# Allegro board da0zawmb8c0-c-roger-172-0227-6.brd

Outline 219.8 x 128 mm; copper layers: TOP, SGND, IN1, IN2, SVCC, IN3, SGND1, BOTTOM. Coordinates in mm from the lower left corner of the outline.

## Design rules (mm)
constraint set DEFAULT: min track width 0.102
net group DFP-S6(5)W6.5(5.5)-T13B: nets M_B_CLKN0 M_B_CLKP0
net group W12-T123B: nets +3V_RTC +3VLCD_CON_R_C
net group DFP-S3.5W4(3.5)-T13B: nets PEX_TSTCLK PEX_TSTCLK# VMA_CLK0 VMA_CLK0# VMA_CLK1 VMA_CLK1# VMA_WCK01 VMA_WCK01# VMA_WCK23 VMA_WCK23# VMA_WCK45 VMA_WCK45# VMA_WCK67 VMA_WCK67#
net group DFP-S4.5W4(3.5)-T13B: nets C_IN_CLK C_IN_CLK# C_IN_CLK#_R C_IN_CLK_R C_TX0_HDMI+ C_TX0_HDMI+_R C_TX0_HDMI- C_TX0_HDMI-_R C_TX1_HDMI+ C_TX1_HDMI+_R C_TX1_HDMI- C_TX1_HDMI-_R C_TX2_HDMI+ C_TX2_HDMI+_R C_TX2_HDMI- C_TX2_HDMI-_R CK_XDP_N CK_XDP_P CLK_PCIE_LANN CLK_PCIE_LANP CLK_PCIE_SSDN CLK_PCIE_SSDP CLK_PCIE_WLANN CLK_PCIE_WLANP CLK_VGA_N CLK_VGA_P IN_CLK#_R IN_CLK_R IN_D0#_R IN_D0_R IN_D1#_R IN_D1_R IN_D2#_R IN_D2_R INT_EDP_AUXN INT_EDP_AUXN_C INT_EDP_AUXP INT_EDP_AUXP_C INT_EDP_TXN0 INT_EDP_TXN0_C INT_EDP_TXN1 INT_EDP_TXN1_C INT_EDP_TXN2 INT_EDP_TXN2_C INT_EDP_TXN3 INT_EDP_TXN3_C INT_EDP_TXP0 INT_EDP_TXP0_C INT_EDP_TXP1 INT_EDP_TXP1_C INT_EDP_TXP2 INT_EDP_TXP2_C INT_EDP_TXP3 INT_EDP_TXP3_C INT_HDMICLK+_OUT INT_HDMICLK-_OUT INT_HDMITX0N_OUT INT_HDMITX0P_OUT INT_HDMITX1N_OUT INT_HDMITX1P_OUT INT_HDMITX2N_OUT INT_HDMITX2P_OUT M_A_CLKN0 M_A_CLKN1 M_A_CLKP0 M_A_CLKP1 M_A_DQSN0 M_A_DQSN1 M_A_DQSN2 M_A_DQSN3 M_A_DQSN4 M_A_DQSN5 M_A_DQSN6 M_A_DQSN7 M_A_DQSP0 M_A_DQSP1 M_A_DQSP2 M_A_DQSP3 M_A_DQSP4 M_A_DQSP5 M_A_DQSP6 M_A_DQSP7 M_B_DQSN0 M_B_DQSN1 M_B_DQSN2 M_B_DQSN3 M_B_DQSN4 M_B_DQSN5 M_B_DQSN6 M_B_DQSN7 M_B_DQSP0 M_B_DQSP1 M_B_DQSP2 M_B_DQSP3 M_B_DQSP4 M_B_DQSP5 M_B_DQSP6 M_B_DQSP7 PCIE_RCOMP PCIE_RCOMP_P PCIE_RXN9_LAN PCIE_RXN10_WLAN PCIE_RXN13_SSD PCIE_RXN13_SSD_C PCIE_RXN14_SSD PCIE_RXN14_SSD_C PCIE_RXN15_SSD PCIE_RXN15_SSD_C PCIE_RXN16_SSD PCIE_RXN16_SSD_C PCIE_RXN_LAN_L PCIE_RXP9_LAN PCIE_RXP10_WLAN PCIE_RXP13_SSD PCIE_RXP13_SSD_C PCIE_RXP14_SSD PCIE_RXP14_SSD_C PCIE_RXP15_SSD PCIE_RXP15_SSD_C PCIE_RXP16_SSD PCIE_RXP16_SSD_C PCIE_RXP_LAN_L PCIE_TXN9_LAN PCIE_TXN9_LAN_C PCIE_TXN10_WLAN PCIE_TXN10_WLAN_C PCIE_TXN13_SSD PCIE_TXN13_SSD_C PCIE_TXN14_SSD PCIE_TXN14_SSD_C PCIE_TXN15_SSD PCIE_TXN15_SSD_C PCIE_TXN16_SSD PCIE_TXN16_SSD_C PCIE_TXP9_LAN PCIE_TXP9_LAN_C PCIE_TXP10_WLAN PCIE_TXP10_WLAN_C PCIE_TXP13_SSD PCIE_TXP13_SSD_C PCIE_TXP14_SSD PCIE_TXP14_SSD_C PCIE_TXP15_SSD PCIE_TXP15_SSD_C PCIE_TXP16_SSD PCIE_TXP16_SSD_C PEG_RXN5 PEG_RXN5_C PEG_RXN6 PEG_RXN6_C PEG_RXN7 PEG_RXN7_C PEG_RXN8 PEG_RXN8_C PEG_RXP5 PEG_RXP5_C PEG_RXP6 PEG_RXP6_C PEG_RXP7 PEG_RXP7_C PEG_RXP8 PEG_RXP8_C PEG_TXN5 PEG_TXN5_C PEG_TXN6 PEG_TXN6_C PEG_TXN7 PEG_TXN7_C PEG_TXN8 PEG_TXN8_C PEG_TXP5 PEG_TXP5_C PEG_TXP6 PEG_TXP6_C PEG_TXP7 PEG_TXP7_C PEG_TXP8 PEG_TXP8_C SATA_RXN0_C SATA_RXN0_CN SATA_RXN0_IN SATA_RXN1A_C SATA_RXN1A_ODD SATA_RXN_OUT SATA_RXP0_C SATA_RXP0_CN SATA_RXP0_IN SATA_RXP1A_C SATA_RXP1A_ODD SATA_RXP_OUT SATA_TXN0_C SATA_TXN0_CN SATA_TXN0_IN SATA_TXN1A_C SATA_TXN1A_ODD SATA_TXN_OUT SATA_TXP0_C SATA_TXP0_CN SATA_TXP0_IN SATA_TXP1A_C SATA_TXP1A_ODD SATA_TXP_OUT USB3_SS0RX+ USB3_SS0RX- USB3_SS0TX+ USB3_SS0TX- USB30_RX1+ USB30_RX1+_C USB30_RX1- USB30_RX1-_C USB30_RX2+ USB30_RX2+_C USB30_RX2- USB30_RX2-_C USB30_RX3+ USB30_RX3- USB30_RX+_TYPEC1 USB30_RX+_TYPEC2 USB30_RX-_TYPEC1 USB30_RX-_TYPEC2 USB30_TX1+ USB30_TX1+_C USB30_TX1+_C_R USB30_TX1- USB30_TX1-_C USB30_TX1-_C_R USB30_TX2+ USB30_TX2+_C USB30_TX2+_C_R USB30_TX2- USB30_TX2-_C USB30_TX2-_C_R USB30_TX3+ USB30_TX3- USB30_TX+_TYPEC1 USB30_TX+_TYPEC1_C USB30_TX+_TYPEC2 USB30_TX+_TYPEC2_C USB30_TX-_TYPEC1 USB30_TX-_TYPEC1_C USB30_TX-_TYPEC2 USB30_TX-_TYPEC2_C USBP1+_C USBP1+_C_R USBP1+_U14 USBP1-_C USBP1-_C_R USBP1-_U14 USBP2+ USBP2+_C USBP2- USBP2-_C USBP3+_TPC USBP3-_TPC USBP4+_DB USBP4-_DB USBP5+_CAM USBP5+_CAM_C USBP5-_CAM USBP5-_CAM_C USBP6+_CR USBP6-_CR USBP7+_FP USBP7-_FP USBP8+_TS USBP8-_TS USBP8_TS+_C USBP8_TS-_C USBP10+_BT USBP10-_BT USBP_TYPC+_C USBP_TYPC-_C
net group DFP-S4.54W4(3.5)-T13B: nets CNV_WR_CLK_DN CNV_WR_CLK_DP CNV_WR_LANE0_DN CNV_WR_LANE0_DP CNV_WR_LANE1_DN CNV_WR_LANE1_DP CNV_WT_CLK_DN CNV_WT_CLK_DP CNV_WT_LANE0_DN CNV_WT_LANE0_DP CNV_WT_LANE1_DN CNV_WT_LANE1_DP
net group DFP-S11.5(11: nets MDI0+ MDI0+_1 MDI0- MDI0-_1 MDI1+ MDI1+_1 MDI1- MDI1-_1 MDI2+ MDI2+_1 MDI2- MDI2-_1 MDI3+ MDI3+_1 MDI3- MDI3-_1
net group GND: nets GND
net group W4(3.5)-T13B: nets 3602_VRHOT ACZ_BCLK ACZ_RST# ACZ_SDIN0 ACZ_SDOUT ACZ_SYNC BIOS_WP# DDR4_DRAMRST# DMIC_CLK DMIC_CLK_2 DMIC_CLK_2_R DMIC_CLK_L DMIC_DAT DMIC_DAT_2 DMIC_DAT_2_R DMIC_DAT_L DNBSWON# DRAM_RESET# EC_PWROK H_PROCHOT# H_VCCST_PWRGD H_VCCST_PWRGD_R HOLD# HWPG IMVP_PWRGD INTRUDER#_R JTAG_TCK_PCH JTAG_TDI_PCH JTAG_TDO_PCH JTAG_TMS_PCH JTAGX_PCH M_A_DQ0 M_A_DQ1 M_A_DQ2 M_A_DQ3 M_A_DQ4 M_A_DQ5 M_A_DQ6 M_A_DQ7 M_A_DQ8 M_A_DQ9 M_A_DQ10 M_A_DQ11 M_A_DQ12 M_A_DQ13 M_A_DQ14 M_A_DQ15 M_A_DQ16 M_A_DQ17 M_A_DQ18 M_A_DQ19 M_A_DQ20 M_A_DQ21 M_A_DQ22 M_A_DQ23 M_A_DQ24 M_A_DQ25 M_A_DQ26 M_A_DQ27 M_A_DQ28 M_A_DQ29 M_A_DQ30 M_A_DQ31 M_A_DQ32 M_A_DQ33 M_A_DQ34 M_A_DQ35 M_A_DQ36 M_A_DQ37 M_A_DQ38 M_A_DQ39 M_A_DQ40 M_A_DQ41 M_A_DQ42 M_A_DQ43 M_A_DQ44 M_A_DQ45 M_A_DQ46 M_A_DQ47 M_A_DQ48 M_A_DQ49 M_A_DQ50 M_A_DQ51 M_A_DQ52 M_A_DQ53 M_A_DQ54 M_A_DQ55 M_A_DQ56 M_A_DQ57 M_A_DQ58 M_A_DQ59 M_A_DQ60 M_A_DQ61 M_A_DQ62 M_A_DQ63 M_B_DQ0 M_B_DQ1 M_B_DQ2 M_B_DQ3 M_B_DQ4 M_B_DQ5 M_B_DQ6 M_B_DQ7 M_B_DQ8 M_B_DQ9 M_B_DQ10 M_B_DQ11 M_B_DQ12 M_B_DQ13 M_B_DQ14 M_B_DQ15 M_B_DQ16 M_B_DQ17 M_B_DQ18 M_B_DQ19 M_B_DQ20 M_B_DQ21 M_B_DQ22 M_B_DQ23 M_B_DQ24 M_B_DQ25 M_B_DQ26 M_B_DQ27 M_B_DQ28 M_B_DQ29 M_B_DQ30 M_B_DQ31 M_B_DQ32 M_B_DQ33 M_B_DQ34 M_B_DQ35 M_B_DQ36 M_B_DQ37 M_B_DQ38 M_B_DQ39 M_B_DQ40 M_B_DQ41 M_B_DQ42 M_B_DQ43 M_B_DQ44 M_B_DQ45 M_B_DQ46 M_B_DQ47 M_B_DQ48 M_B_DQ49 M_B_DQ50 M_B_DQ51 M_B_DQ52 M_B_DQ53 M_B_DQ54 M_B_DQ55 M_B_DQ56 M_B_DQ57 M_B_DQ58 M_B_DQ59 M_B_DQ60 M_B_DQ61 M_B_DQ62 M_B_DQ63 PCH_AZ_CODEC_BITCLK PCH_AZ_CODEC_RST# PCH_AZ_CODEC_SDIN0 PCH_AZ_CODEC_SDOUT PCH_AZ_CODEC_SYNC PCH_SPI1_CLK PCH_SPI1_CLK_R PCH_SPI1_SI PCH_SPI1_SI_R PCH_SPI1_SO PCH_SPI1_SO_R PCH_SPI_CS0# PCH_SPI_CS0#_R PCH_SPI_IO2 PCH_SPI_IO3 PEGX_RST# PEGX_RST#_C PEX_TERMP PLTRST# PROC_TRST# PROCHOT# PROCHOT_EC PROCPWRGD RSMRST# SIO_RCIN# SPI_TPM_CS# SYS_PWROK SYS_RESET# TESTMODE USB_OC2# XDP_BPM0 XDP_BPM1 XDP_TCK0 XDP_TDI_CPU XDP_TDO_CPU XDP_TMS_CPU XDP_TRST#_CPU
net group W4(3.5)-T123B: nets 2ND_MBCLK 2ND_MBDATA 5V_HSMBCK 5V_HSMBDT 27M_XTAL_IN 27M_XTAL_OUT 3602_ALERT# 3602_CLK 3602_VDIO BRIGHT CLK_24M_DEBUG CLK_PCI_EC CLK_PCI_EC_R CLK_PCI_LPC_R CNV_BRI_DT CNV_BRI_DT_R CNV_BRI_RSP CNV_BRI_RSP_L CNV_RGI_DT CNV_RGI_DT_R CNV_RGI_RSP CNV_RGI_RSP_L COMP_CORE COMP_GT COMP_SA DDCCLK_RIN DDCDATA_RIN DISP_ON EC_PECI EC_PECR_R FB_SA GPUT_CLK_L GPUT_DATA_L H_CPU_SVIDALRT# H_CPU_SVIDCLK H_CPU_SVIDDAT H_CPU_SVIDDAT_R HDMI_HPD HDMI_HPD_C HDMI_HPD_CON HDMI_MB_HPD_R HDMI_SCLK HDMI_SDATA LAD0_R LFRAME#_R LPC_LAD0 LPC_LAD1 LPC_LAD2 LPC_LAD3 LPC_LFRAME# PCH_BLON_C PCH_DISP_ON PCH_DPST_PWM PCH_LVDS_BLON PCIE_CLKREQ_LAN# PCIE_CLKREQ_SSD# PCIE_CLKREQ_VGA# PCIE_CLKREQ_WLAN# PULSAR_38P4M_REFCLK PULSAR_38P4M_REFCLK_R PWM-VID RGND_CORE RGND_GT RGND_SA RTC_RST# RTC_X1 RTC_X2 SDVO_CLK SDVO_DATA SMB_ME0_CLK SMB_ME0_DAT SMB_ME1_CLK SMB_ME1_DAT SMB_PCH_CLK SMB_PCH_DAT SMB_RUN_CLK SMB_RUN_DAT SRTC_RST# SUSCLK_32K SUSCLK_32KHZ SYS_SHDN# THERMTRIP# THERMTRIP#_CPU TP_I2C_CLK TP_I2C_DATA TP_SMB_CLK TP_SMB_DATA ULT_EDP_HPD ULT_EDP_HPD_R VCCGT_SENSE VCORE_SENSE VCORESS_SENSE VGA_VCCSENSE VGA_VSSSENSE VR_SVID_ALERT#_VCORE VR_SVID_CLK_R VSEN_CORE VSEN_GT VSEN_SA VSSGT_SENSE XCLK_BIASREF XTAL24_IN XTAL24_OUT
net group W4-T13B: nets CFG_RCOMP CNV_WT_RCOMP EDRAM_OPIO_RCOMP EMMC_RCOMP EOPIO_RCOMP PCH_OPI_RCOMP PROC_POPIRCOMP SD_1P8_RCOPM USB2_COMP
net group W4-T123B: nets +1.2VSUS
net group W5(4)-T13B: nets M_A_A0 M_A_A1 M_A_A2 M_A_A3 M_A_A4 M_A_A5 M_A_A6 M_A_A7 M_A_A8 M_A_A9 M_A_A10 M_A_A11 M_A_A12 M_A_A13 M_A_ACT# M_A_ALERT# M_A_BG#0 M_A_BG#1 M_A_BS#0 M_A_BS#1 M_A_CAS# M_A_CKE0 M_A_CKE1 M_A_CS#0 M_A_CS#1 M_A_DIM0_ODT0 M_A_DIM0_ODT1 M_A_PARITY M_A_RAS# M_A_WE#
net group W5(4.5: nets FBA_CMD0 FBA_CMD1 FBA_CMD2 FBA_CMD3 FBA_CMD4 FBA_CMD5 FBA_CMD6 FBA_CMD7 FBA_CMD8 FBA_CMD9 FBA_CMD10 FBA_CMD11 FBA_CMD12 FBA_CMD13 FBA_CMD14 FBA_CMD15 FBA_CMD16 FBA_CMD17 FBA_CMD18 FBA_CMD19 FBA_CMD20 FBA_CMD21 FBA_CMD22 FBA_CMD23 FBA_CMD24 FBA_CMD25 FBA_CMD26 FBA_CMD27 FBA_CMD28 FBA_CMD29 FBA_CMD30 FBA_CMD31
net group W5-T13B: nets EDP_RCOMP
net group W6.5(5.5)-T13B: nets M_B_A0 M_B_A1 M_B_A2 M_B_A3 M_B_A4 M_B_A5 M_B_A6 M_B_A7 M_B_A8 M_B_A9 M_B_A10 M_B_A11 M_B_A12 M_B_A13 M_B_ACT# M_B_ALERT# M_B_BG#0 M_B_BG#1 M_B_BS#0 M_B_BS#1 M_B_CAS# M_B_CKE0 M_B_CS#0 M_B_DIM0_ODT0 M_B_PARITY M_B_RAS# M_B_WE#
net group W6.5(6: nets FBA_DBI0 FBA_DBI1 FBA_DBI2 FBA_DBI3 FBA_DBI4 FBA_DBI5 FBA_DBI6 FBA_DBI7 FBA_EDC0 FBA_EDC1 FBA_EDC2 FBA_EDC3 FBA_EDC4 FBA_EDC5 FBA_EDC6 FBA_EDC7 VMA_DQ0 VMA_DQ1 VMA_DQ2 VMA_DQ3 VMA_DQ4 VMA_DQ5 VMA_DQ6 VMA_DQ7 VMA_DQ8 VMA_DQ9 VMA_DQ10 VMA_DQ11 VMA_DQ12 VMA_DQ13 VMA_DQ14 VMA_DQ15 VMA_DQ16 VMA_DQ17 VMA_DQ18 VMA_DQ19 VMA_DQ20 VMA_DQ21 VMA_DQ22 VMA_DQ23 VMA_DQ24 VMA_DQ25 VMA_DQ26 VMA_DQ27 VMA_DQ28 VMA_DQ29 VMA_DQ30 VMA_DQ31 VMA_DQ32 VMA_DQ33 VMA_DQ34 VMA_DQ35 VMA_DQ36 VMA_DQ37 VMA_DQ38 VMA_DQ39 VMA_DQ40 VMA_DQ41 VMA_DQ42 VMA_DQ43 VMA_DQ44 VMA_DQ45 VMA_DQ46 VMA_DQ47 VMA_DQ48 VMA_DQ49 VMA_DQ50 VMA_DQ51 VMA_DQ52 VMA_DQ53 VMA_DQ54 VMA_DQ55 VMA_DQ56 VMA_DQ57 VMA_DQ58 VMA_DQ59 VMA_DQ60 VMA_DQ61 VMA_DQ62 VMA_DQ63
net group W8-T123B: nets +1.05V_LAN +1.8V_SW +1V8_AON +3V +3V3_TPM +3V_DEEP_SUS +3V_LDO_EC +3V_S5 +3V_WLAN_P +3VPCU_EC +3VSPI +5V_PVDD +5VA +5VPCU +A3VPCU +AZA_VDD +G_SEN_PW +USBPWR0 +USBPWR1 +VCCIO +VCCST +VIN AVDD2 DVDD_IO VCCDSW_1P05 VCCPRIM_1P8
net group W10-T123B: nets +1.05V_DEEP_SUS +1.8V_DEEP_SUS +1.8V_S5 +1V8_GFX_MAIN +3V_EC +3VPCU_ECPLL +TYPEC_VBUS_C +VDDQ_VTT +VGPU_CORE DCPRTC NV_PLLVDD RSET SP_PLLVDD VCCA_19P2_1P05 VCCA_OC_1P05 VCCA_SRC_1P05 VCCA_XTAL_1P05 VCCDSW_3P32
net group W13-T123B: nets +1.35V_GFX
net group W14-T123B: nets +2.5V_SUS
net group W15-T13B: nets SM_RCOMP_0 SM_RCOMP_1 SM_RCOMP_2
net group W15-T123B: nets +3V_DMIC +VCCLDOSRAM_1P24 FB_CAL_PD_VDDQ HP-L2 HP-L3 HP-R2 HP-R3 HP_JD# LINE1-L LINE1-R LINE1-VREFO-L LINE1-VREFO-R MIC2-VREFO SENSEA
net group W20-T123B: nets +3V_LAN +3V_RTC_0 +3V_RTC_1 +3V_RTC_2 +5V_FAN +5V_HDMIC +SMDDR_VREF_DIMM +SMDDR_VREF_DQ1_M1 +VCCPLL +VCCPLL_OC +VCCRTC +VCCSTG +VDDQ FB_CAL_TERM_GND FBA_VREFC_1 FBA_VREFC_2 PBA_PWR PBA_PWR_C PBA_PWR_R SM_VREF SMDDR_VREF_DQ1_M3 VCCAPLL_1.05V VCCDPHY_1P24 VCCDSW_GPIO VCCDUSB_1P05 VCCHDA VCCSPI
net group W30-T123B: nets +5V_KB
net group W40-T123B: nets +1.03_GFX +3VLCD_CON +3VLCD_CON_R +601_VCC L_SPK+ L_SPK+_1 L_SPK- L_SPK-_1 R_SPK+ R_SPK+_1 R_SPK- R_SPK-_1 RING2 SLEEVE VCCMPHYGTAON_1P05
net group W60-T123B: nets +1.05V_LAN_REGOUT
net group W80-T123B: nets +VIN_BLIGHT VCCPRIM_1P05 VCCPRIM_3P3
net group W99-T123B: nets +3V_SSD +5VODD +TYPEC_VBUS +VCC_CORE +VCCSA
nets with their own width: min track width 0.305; nets I2CA_SCL I2CA_SDA

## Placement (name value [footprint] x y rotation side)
C1  0.033u/16V_4  [C0402]  92.06 36.44 0 top
C2  *0.033u/16V_4  [C0402]  92.06 37.4 180 top
C3  *0.1U/16V_2  [C0201]  49.85 31.48 90 top
C5  *0.47u/6.3V_2  [C0201]  67.22 40.15 270 bottom
C6  *0.47u/6.3V_2  [C0201]  81.72 46.57 90 top
C7  *0.1u/16V_2  [C0201]  92.59 29.53 90 bottom
C8  0.01u/50V_4  [C0402]  66.36 44.69 90 top
C9  *10P/50V_4  [C0402]  102.09 54.32 90 bottom
C11  *10U/6.3V_4  [C0402]  84.83 55.52 90 top
C12  10u/6.3V_4  [C0402]  83.87 55.52 90 top
C13  *22U/6.3V_6  [C0603]  107.3 67.85 270 top
C14  10u/6.3V_4  [C0402]  83.77 53.53 270 top
C15  22U/6.3V_6  [C0603]  103.4 64.21 90 bottom
C16  1u/6.3V_2  [C0201]  93.76 56.7 90 top
C17  1u/6.3V_2  [C0201]  93.43 57.69 90 top
C18  1u/6.3V_2  [C0201]  92.34 53.43 180 top
C19  22U/6.3V_6  [C0603]  104.86 63.99 90 bottom
C20  10u/6.3V_4  [C0402]  85.79 55.52 90 top
C21  22U/6.3V_6  [C0603]  88.27 57.95 90 top
C22  1u/6.3V_2  [C0201]  90.53 59.17 0 top
C23  1u/6.3V_2  [C0201]  90.43 57.83 270 top
C24  1u/6.3V_2  [C0201]  81.89 54.97 90 top
C25  1u/6.3V_2  [C0201]  94.65 58.43 90 top
C26  22U/6.3V_6  [C0603]  104.02 67.8 270 bottom
C27  *22U/6.3V_6  [C0603]  112.08 58.08 0 bottom
C28  22U/6.3V_6  [C0603]  105.45 67.8 270 bottom
C29  *330u/2.5V_3528H1.9  [C3528]  114.23 64.43 180 bottom
C30  10u/6.3V_4  [C0402]  84.73 53.53 270 top
C31  10u/6.3V_4  [C0402_2]  81.89 56.69 90 top
C32  1u/6.3V_2  [C0201]  90.46 54.29 270 top
C33  1u/6.3V_2  [C0201]  89.5 54.28 270 top
C34  1u/6.3V_2  [C0201]  90.46 56.02 90 top
C35  1u/6.3V_2  [C0201]  89.34 52.56 90 top
C36  1u/6.3V_2  [C0201]  93.58 55.26 90 top
C37  1u/6.3V_2  [C0201]  95.01 56.98 270 top
C38  1u/6.3V_2  [C0201]  89.47 57.83 270 top
C39  1u/6.3V_2  [C0201]  89.5 56.02 90 top
C40  10u/6.3V_4  [C0402]  90.31 52.56 270 top
C41  10u/6.3V_4  [C0402_2]  81.89 58.41 270 top
C42  10u/6.3V_4  [C0402_2]  86.9 55.54 90 top
C43  10u/6.3V_4  [C0402_2]  87 53.53 270 top
C44  *22U/6.3V_6  [C0603]  110.15 67.85 270 top
C45  10u/6.3V_4  [C0402_2]  85.81 53.53 270 top
C46  *22U/6.3V_6  [C0603]  108.72 67.85 270 top
C47  0.1u/16V_2  [C0201]  81.89 53.25 90 top
C48  *22U/6.3V_6  [C0603]  83.96 57.96 90 top
C49  *22U/6.3V_6  [C0603]  85.39 57.96 90 top
C50  *22U/6.3V_6  [C0603]  112.46 54.72 0 top
C51  *22U/6.3V_6  [C0603]  112.46 53.3 0 top
C52  *22U/6.3V_6  [C0603]  86.83 57.95 90 top
C53  *22U/6.3V_6  [C0603]  88.3 55.31 270 top
C54  *22U/6.3V_6  [C0603]  112.46 51.88 0 top
C55  22U/6.3V_6  [C0603]  106.74 52.82 270 bottom
C56  10u/6.3V_4  [C0402_2]  107.94 47.28 90 top
C57  10u/6.3V_4  [C0402_2]  102.12 45.86 270 top
C58  47U/6.3VS_6  [C0603]  108.27 52.84 270 bottom
C59  47U/6.3VS_6  [C0603]  109.79 52.85 270 bottom
C60  *47U/6.3VS_6  [C0603]  111.31 52.85 270 bottom
C61  47U/6.3VS_6  [C0603]  107.73 63.99 90 bottom
C62  47U/6.3VS_6  [C0603]  106.28 63.99 90 bottom
C63  47U/6.3VS_6  [C0603]  108.29 67.8 270 bottom
C64  47U/6.3VS_6  [C0603]  106.87 67.8 270 bottom
C65  47U/6.3VS_6  [C0603]  109.15 63.99 90 bottom
C66  10u/6.3V_4  [C0402_2]  116.19 59.98 0 top
C67  10u/6.3V_4  [C0402_2]  116.19 58.71 0 top
C68  *22U/6.3V_6  [C0603]  112.08 59.5 0 bottom
C69  10u/6.3V_4  [C0402_2]  100.77 64.63 270 bottom
C70  10u/6.3V_4  [C0402_2]  102.04 64.63 270 bottom
C71  10u/6.3V_4  [C0402_2]  116.19 61.25 0 top
C72  10u/6.3V_4  [C0402_2]  102.5 67.8 90 bottom
C73  *22U/6.3V_6  [C0603]  112.05 60.92 0 bottom
C74  10u/6.3V_4  [C0402]  66.36 69.99 90 top
C75  1u/6.3V_2  [C0201]  64.32 69.99 270 top
C76  1u/6.3V_2  [C0201]  77.4 66.53 90 top
C77  10u/6.3V_4  [C0402]  77.4 53.83 270 top
C78  1u/6.3V_2  [C0201]  83.09 61.84 270 top
C79  1u/6.3V_2  [C0201]  81.98 51.83 180 top
C80  1u/6.3V_2  [C0201]  86.93 48.63 270 top
C81  10u/6.3V_4  [C0402_2]  81.9 61.85 90 top
C82  10u/6.3V_4  [C0402_2]  83.14 60.13 270 top
C83  10u/6.3V_4  [C0402_2]  81.89 60.13 270 top
C84  1u/6.3V_2  [C0201]  103.01 38.42 90 top
C85  1u/6.3V_2  [C0201]  103.74 38.44 90 top
C86  1u/6.3V_2  [C0201]  82.05 50.48 270 top
C87  1u/6.3V_2  [C0201]  77.3 56.07 90 top
C88  1u/6.3V_2  [C0201]  65.34 69.99 270 top
C89  1u/6.3V_2  [C0201]  104.46 38.06 90 top
C90  10u/6.3V_4  [C0402]  65.34 64.63 90 top
C91  10u/6.3V_4  [C0402]  64.32 64.63 90 top
C92  10u/6.3V_4  [C0402]  62.67 76.31 90 top
C93  10u/6.3V_4  [C0402]  65.34 56.63 270 top
C94  *10U/6.3V_4  [C0402]  63.31 69.99 90 top
C95  1u/6.3V_2  [C0201]  77.4 51.78 90 top
C96  1u/6.3V_2  [C0201]  107.55 51.78 270 top
C97  1u/6.3V_2  [C0201]  83.8 52.04 270 top
C98  1u/6.3V_2  [C0201]  86.1 50.32 90 top
C99  1u/6.3V_2  [C0201]  110.07 49.01 90 top
C100  1u/6.3V_2  [C0201]  88.02 50.32 90 top
C101  1u/6.3V_2  [C0201]  84.76 52.04 270 top
C102  1u/6.3V_2  [C0201]  87.06 50.32 90 top
C103  10u/6.3V_4  [C0402_2]  88.32 51.8 90 top
C104  10u/6.3V_4  [C0402]  108.47 51.8 90 top
C105  10u/6.3V_4  [C0402_2]  85.95 51.78 90 top
C106  10u/6.3V_4  [C0402]  84.83 50.32 270 top
C107  10u/6.3V_4  [C0402_2]  87.13 51.78 90 top
C108  10u/6.3V_4  [C0402]  107.2 49.01 270 top
C109  10u/6.3V_4  [C0402]  83.87 50.32 270 top
C110  10u/6.3V_4  [C0402]  109.43 51.8 90 top
C111  10u/6.3V_4  [C0402]  108.22 49.01 270 top
C112  10u/6.3V_4  [C0402]  109.23 49.01 270 top
C113  10u/6.3V_4  [C0402]  106.18 49.01 270 top
C114  10u/6.3V_4  [C0402_2]  111.03 48.93 270 top
C115  10u/6.3V_4  [C0402_2]  110.53 51.8 90 top
C116  1u/6.3V_2  [C0201]  100.65 56.37 270 bottom
C117  1u/6.3V_2  [C0201]  65.34 54.72 270 top
C118  1u/6.3V_2  [C0201]  106.97 47.64 90 top
C119  22U/6.3V_6  [C0603]  109.33 46.82 270 top
C122  1u/6.3V_2  [C0201]  106.26 47.64 270 top
C123  1u/6.3V_2  [C0201]  101.15 45.58 90 top
C124  10u/6.3V_4  [C0402]  64.32 60.44 270 top
C125  10u/6.3V_4  [C0402]  63.31 56.63 90 top
C126  10u/6.3V_4  [C0402]  64.32 56.63 90 top
C127  10u/6.3V_4  [C0402]  63.31 60.44 270 top
C128  10u/6.3V_4  [C0402]  62.29 60.44 270 top
C129  10u/6.3V_4  [C0402]  62.29 69.99 270 top
C130  1u/6.3V_2  [C0201]  62.29 56.63 90 top
C131  1u/6.3V_2  [C0201]  65.34 60.44 270 top
C132  1u/6.3V_2  [C0201]  63.31 64.63 270 top
C133  1u/6.3V_2  [C0201]  62.29 64.63 270 top
C134  47U/6.3VS_6  [C0603]  98.64 78.42 90 top
C135  10u/6.3V_4  [C0402_2]  82 72.68 180 top
C136  10u/6.3V_4  [C0402_2]  84.39 70.21 0 top
C137  10u/6.3V_4  [C0402_2]  90.49 81.39 180 top
C138  22U/6.3V_6  [C0603]  83.15 88.63 90 bottom
C139  22U/6.3V_6  [C0603]  77.79 92.24 180 bottom
C140  22U/6.3V_6  [C0603]  94.55 82.54 180 top
C141  22U/6.3V_6  [C0603]  91.88 82.79 180 top
C142  10u/6.3V_4  [C0402]  90.13 60.96 270 top
C143  10u/6.3V_4  [C0402]  89.44 66.18 90 top
C144  10u/6.3V_4  [C0402_2]  90.28 64.45 270 top
C145  22U/6.3V_6  [C0603]  94.25 84.82 270 top
C146  22U/6.3V_6  [C0603]  92.54 84.82 270 top
C147  22U/6.3V_6  [C0603]  90.97 84.82 270 top
C148  22U/6.3V_6  [C0603]  86.09 88.63 270 bottom
C149  22U/6.3V_6  [C0603]  77.89 90.82 0 bottom
C150  10u/6.3V_4  [C0402_2]  88.58 83.17 90 top
C151  10u/6.3V_4  [C0402_2]  82 71.46 180 top
C152  10u/6.3V_4  [C0402_2]  84.45 68.95 0 top
C153  10u/6.3V_4  [C0402_2]  86.22 68.97 180 top
C154  10u/6.3V_4  [C0402_2]  82 70.24 180 top
C155  10u/6.3V_4  [C0402]  82 67.14 180 top
C156  10u/6.3V_4  [C0402]  82 68.11 180 top
C157  10u/6.3V_4  [C0402_2]  92.14 80.61 270 top
C158  10u/6.3V_4  [C0402]  82 69.12 180 top
C159  22U/6.3V_6  [C0603]  84.67 88.63 90 bottom
C160  22U/6.3V_6  [C0603]  81.21 90.66 0 bottom
C161  22U/6.3V_6  [C0603]  96.43 77.89 0 top
C162  10u/6.3V_4  [C0402_2]  93.53 61.56 270 top
C163  10u/6.3V_4  [C0402]  92.26 63.18 90 top
C164  10u/6.3V_4  [C0402]  92.26 61.02 270 top
C165  10u/6.3V_4  [C0402_2]  90.28 62.72 90 top
C166  22U/6.3V_6  [C0603]  87.39 84.95 0 top
C167  22U/6.3V_6  [C0603]  95.67 84.82 90 top
C168  22U/6.3V_6  [C0603]  81.21 92.09 0 bottom
C169  22U/6.3V_6  [C0603]  100.06 78.42 90 top
C170  22U/6.3V_6  [C0603]  84.67 63.82 270 top
C171  22U/6.3V_6  [C0603]  86.09 63.82 270 top
C172  22U/6.3V_6  [C0603]  87.51 63.82 90 top
C173  22U/6.3V_6  [C0603]  88.96 63.82 90 top
C174  22U/6.3V_6  [C0603]  82.21 64.4 180 top
C175  22U/6.3V_6  [C0603]  82.22 65.93 180 top
C176  22U/6.3V_6  [C0603]  88.25 66.48 270 top
C177  1u/6.3V_2  [C0201]  86.8 83.17 180 bottom
C178  1u/6.3V_2  [C0201]  88.33 83.93 0 bottom
C179  1u/6.3V_2  [C0201]  86.8 83.93 180 bottom
C180  1u/6.3V_2  [C0201]  86.8 82.41 180 bottom
C181  1u/6.3V_2  [C0201]  90.99 83.93 0 bottom
C182  1u/6.3V_2  [C0201]  88.33 83.17 0 bottom
C183  1u/6.3V_2  [C0201]  89.47 83.17 180 bottom
C184  1u/6.3V_2  [C0201]  90.99 82.41 0 bottom
C185  1u/6.3V_2  [C0201]  89.47 83.93 180 bottom
C186  1u/6.3V_2  [C0201]  89.47 82.41 180 bottom
C187  1u/6.3V_2  [C0201]  90.99 83.17 0 bottom
C188  1u/6.3V_2  [C0201]  88.33 82.41 0 bottom
C189  1u/6.3V_2  [C0201]  158.05 31.99 0 top
C190  0.1u/16V_2  [C0201]  163.51 33.51 90 top
C191  *22p/50V_4  [C0402]  161.99 34.56 270 top
C192  0.22u/10V_2  [C0201]  101.28 42.79 0 bottom
C193  0.22u/10V_2  [C0201]  101.28 42.07 0 bottom
C194  0.22u/10V_2  [C0201]  104.33 43.14 0 bottom
C195  0.22u/10V_2  [C0201]  104.33 43.85 0 bottom
C200  0.1u/16V_2  [C0201]  100.65 45.48 0 bottom
C201  0.1u/16V_2  [C0201]  100.65 46.19 0 bottom
C202  0.1u/16V_2  [C0201]  181.49 23.18 90 bottom
C203  0.1u/16V_2  [C0201]  180.78 23.18 90 bottom
C204  *2.2p/50V_4  [C0402]  98.54 35.42 90 top
C205  10P/50V_4  [C0402]  99.17 28.79 180 bottom
C206  15p/50V_4  [C0402]  76.13 30.85 180 bottom
C208  10P/50V_4  [C0402]  100.9 28.79 0 bottom
C209  15p/50V_4  [C0402]  79.67 31.33 0 bottom
C212  *0.1u/16V_2  [C0201]  44.84 22.36 270 top
C213  3p/50V_4  [C0402]  63.94 47.61 180 bottom
C214  3p/50V_4  [C0402]  63.61 49.52 90 bottom
C215  3p/50V_4  [C0402]  64.96 44.56 270 bottom
C216  15p/50V_4  [C0402]  62.93 52.06 0 top
C217  15p/50V_4  [C0402]  64.58 49.52 90 bottom
C218  15p/50V_4  [C0402]  64.83 46.21 180 bottom
C219  0.1u/16V_2  [C0201]  98.64 36.82 0 top
C220  1u/6.3V_2  [C0201]  87.46 30.92 180 bottom
C221  0.1u/16V_2  [C0201]  87.46 31.63 180 bottom
C222  1u/6.3V_2  [C0201]  99.88 35.9 180 top
C223  1u/6.3V_2  [C0201]  85.56 48.55 270 top
C224  1u/6.3V_2  [C0201]  97.09 31.48 180 top
C225  1u/6.3V_2  [C0201]  83.27 48.55 270 top
C226  1u/6.3V_2  [C0201]  101.1 35.06 0 bottom
C227  1u/6.3V_2  [C0201]  99.88 29.45 270 top
C228  4.7u/6.3V_4  [C0402]  82.31 31.48 0 bottom
C229  1u/6.3V_2  [C0201]  83.93 46.26 180 top
C230  10u/6.3V_4  [C0402]  96.96 31.51 0 bottom
C231  3p/50V_4  [C0402]  102.17 39.41 0 top
C232  3p/50V_4  [C0402]  99.88 42.79 270 top
C233  10u/6.3V_4  [C0402]  102.63 28.66 180 bottom
C234  10u/6.3V_4  [C0402]  102.63 29.63 180 bottom
C235  1u/6.3V_2  [C0201]  100.26 45.33 180 top
C236  1u/6.3V_2  [C0201]  84.14 30.8 90 top
C237  1u/6.3V_2  [C0201]  88.43 33.4 180 top
C238  1u/6.3V_2  [C0201]  84.8 48.55 270 top
C239  *0.1u/16V_2  [C0201]  66.41 26.91 0 top
C240  1u/6.3V_2  [C0201]  66.46 26.15 0 top
C241  3p/50V_4  [C0402]  88.78 31.6 180 top
C242  1u/6.3V_2  [C0201]  63.31 28.05 0 bottom
C243  3p/50V_4  [C0402]  89.52 28.48 180 top
C244  1u/6.3V_2  [C0201]  107.58 30.42 0 bottom
C245  47U/6.3V_6  [C0603]  107 31.58 0 bottom
C246  0.1u/16V_2  [C0201]  63.69 23.35 180 top
C247  *10P/50V_4  [C0402]  60.16 26.12 270 bottom
C248  *0.1U/16V_2  [C0201]  115.68 22.85 180 top
C249  *0.1u/6.3V_2  [C0201]  50.23 69.46 180 top
C250  1u/6.3V_4  [C0402]  50.23 61.07 180 top
C251  1u/6.3V_4  [C0402]  47.76 28.94 90 top
C252  1u/6.3V_4  [C0402]  52.64 47.1 0 top
C253  1u/6.3V_4  [C0402]  49.69 28.94 90 top
C254  1u/6.3V_4  [C0402]  58.23 55.74 0 top
C255  1u/6.3V_4  [C0402]  48.73 28.94 90 top
C256  1u/6.3V_4  [C0402]  50.23 63.87 180 top
C257  1u/6.3V_4  [C0402]  50.73 28.94 90 top
C258  1u/6.3V_4  [C0402]  49.85 40.5 270 top
C259  10u/6.3V_4  [C0402]  46.8 28.94 90 top
C260  1u/6.3V_4  [C0402]  50.48 55.87 180 top
C261  10u/6.3V_4  [C0402]  50.73 30.97 270 top
C262  1u/6.3V_4  [C0402]  58.35 65.65 0 top
C263  1u/6.3V_4  [C0402]  58.35 61.2 0 top
C264  0.1u/6.3V_2  [C0201]  49.97 53.58 0 top
C265  2.2U/10V_4  [C0402]  50.35 52.56 180 top
C266  0.022u/25V_4  [C0402]  50.23 44.94 0 top
C267  10u/6.3V_4  [C0402]  58.35 53.71 0 top
C268  10u/6.3V_4  [C0402]  58.48 57.77 0 top
C269  1u/6.3V_4  [C0402]  52.26 29.96 0 top
C270  10u/6.3V_4  [C0402]  50.23 72.5 180 top
C271  1u/6.3V_4  [C0402]  52.26 28.33 0 top
C272  10u/6.3V_4  [C0402]  60.26 69.58 180 top
C273  10u/6.3V_4  [C0402]  52.13 31.3 0 top
C274  10u/6.3V_4  [C0402]  50.23 65.39 180 top
C275  10u/6.3V_4  [C0402]  54.04 31.74 270 top
C276  10u/6.3V_4  [C0402]  58.48 77.2 0 top
C277  10u/6.3V_4  [C0402]  56.2 68.01 0 top
C278  0.1u/6.3V_2  [C0201]  55.94 31.99 90 top
C279  10u/6.3V_4  [C0402]  50.23 68.44 180 top
C280  2.2U/10V_4  [C0402]  55.05 32.12 270 top
C281  68p/50V_4  [C0402]  32.95 34.53 270 top
C282  68p/50V_4  [C0402]  30.16 50.41 180 top
C283  68p/50V_4  [C0402]  46.67 82.79 180 top
C284  68p/50V_4  [C0402]  48.47 96.51 90 top
C285  1u/6.3V_4  [C0402]  43.62 61.45 0 top
C286  1u/6.3V_4  [C0402]  45.65 61.45 0 top
C287  1u/6.3V_4  [C0402]  31.05 99.17 270 top
C288  1u/6.3V_4  [C0402]  26.86 90.28 0 top
C289  1u/6.3V_4  [C0402]  44.38 48.12 0 top
C290  1u/6.3V_4  [C0402]  37.15 99.17 270 top
C291  1u/6.3V_4  [C0402]  41.21 99.17 270 top
C292  1u/6.3V_4  [C0402]  41.21 82.79 180 top
C293  1u/6.3V_4  [C0402]  35.11 99.17 270 top
C294  1u/6.3V_4  [C0402]  26.86 86.73 0 top
C295  1u/6.3V_4  [C0402]  40.07 69.46 180 top
C296  1u/6.3V_4  [C0402]  26.86 92.7 0 top
C297  1u/6.3V_4  [C0402]  39.18 99.17 270 top
C298  1u/6.3V_4  [C0402]  30.16 38.34 0 top
C299  0.022u/25V_4  [C0402]  53.66 99.17 180 top
C300  1u/6.3V_4  [C0402]  45.58 96.51 270 top
C301  10u/6.3V_4  [C0402_2]  26.86 88.89 0 top
C302  10u/6.3V_4  [C0402_2]  33.08 99.17 270 top
C303  1u/6.3V_4  [C0402]  50.35 88.89 180 top
C304  1u/6.3V_4  [C0402]  46.04 69.46 0 top
C305  1u/6.3V_4  [C0402]  34.35 61.33 0 top
C306  1u/6.3V_4  [C0402]  30.16 51.42 0 top
C307  10u/6.3V_4  [C0402_2]  30.19 59.83 0 top
C308  10u/6.3V_4  [C0402_2]  37.91 34.78 0 top
C309  10u/6.3V_4  [C0402_2]  43.37 34.78 0 top
C310  3.3p/50V_4  [C0402]  30.67 88 270 top
C311  10u/6.3V_4  [C0402_2]  30.16 37.2 0 top
C312  0.1u/16V_4  [C0402]  37.27 48.12 180 top
C313  10u/6.3V_4  [C0402_2]  30.16 73.52 0 top
C314  2.2u/6.3V_4  [C0402]  45.4 98.54 90 top
C315  1u/6.3V_4  [C0402]  30.67 79.87 90 top
C316  1u/6.3V_4  [C0402]  50.23 86.35 180 top
C317  0.047u/25V_4  [C0402]  36.13 61.33 180 top
C318  1u/6.3V_4  [C0402]  40.04 61.33 180 top
C319  1u/6.3V_4  [C0402]  39.05 48.12 0 top
C320  0.047u/25V_4  [C0402]  37.65 82.79 180 top
C321  1u/6.3V_4  [C0402]  50.35 90.66 180 top
C322  0.01u/50V_4  [C0402]  36.26 69.46 180 top
C323  0.047u/25V_4  [C0402]  46.42 98.54 270 top
C324  0.01u/50V_4  [C0402]  38.16 69.46 0 top
C325  0.01u/50V_4  [C0402]  46.54 96.51 90 top
C326  0.047u/25V_4  [C0402]  37.91 61.33 0 top
C327  0.01u/50V_4  [C0402]  47.51 96.51 90 top
C328  0.01u/50V_4  [C0402]  50.35 93.33 0 top
C329  1u/6.3V_4  [C0402]  30.16 48.37 0 top
C330  1u/6.3V_4  [C0402]  31.94 34.53 90 top
C331  1u/6.3V_4  [C0402]  49.44 96.51 270 top
C332  1u/6.3V_4  [C0402]  48.45 82.79 180 top
C333  1u/6.3V_4  [C0402]  30.16 49.39 0 top
C334  1u/6.3V_4  [C0402]  28.81 82.97 270 top
C335  1u/6.3V_4  [C0402]  50.4 96.51 270 top
C336  3.3p/50V_4  [C0402]  48.45 98.54 270 top
C337  68p/50V_4  [C0402]  39.43 82.79 0 top
C338  2200p/50V_4  [C0402]  35.49 48.12 180 top
C339  68p/50V_4  [C0402]  45.15 34.78 0 top
C340  2200p/50V_4  [C0402]  46.16 48.12 0 top
C341  1u/6.3V_4  [C0402]  29.83 82.97 270 top
C342  0.1u/16V_4  [C0402]  50.35 81.77 0 top
C343  3.3p/50V_4  [C0402]  50.23 95.11 0 top
C344  10u/6.3V_4  [C0402_2]  30.8 34.53 90 top
C345  10u/6.3V_4  [C0402_2]  30.16 70.85 0 top
C346  68p/50V_4  [C0402]  30.16 72 180 top
C347  EV@22U/6.3VS_4  [C0402]  117.54 122.54 180 bottom
C348  EV@10u/6.3V_4  [C0402]  117.16 121.53 180 bottom
C349  EV@4.7u/6.3V_4  [C0402_2]  119.24 120.43 0 bottom
C350  EV@4.7u/6.3V_4  [C0402_2]  117.16 120.43 180 bottom
C351  EV@1u/6.3V_4  [C0402]  104.07 105.9 270 top
C352  EV@1u/6.3V_4  [C0402]  108.11 105.9 270 top
C353  EV@1u/6.3V_4  [C0402]  109.54 102.09 90 top
C354  EV@1u/6.3V_4  [C0402]  111.26 110.58 270 top
C355  EV@47U/6.3V_6  [C0603]  111.06 120.38 0 bottom
C356  EV@4.7u/6.3V_4  [C0402_2]  113.35 120.38 180 bottom
C357  EV@4.7u/6.3V_4  [C0402_2]  108.16 104.13 90 top
C358  EV@0.22u/10V_4  [C0402]  98.11 109.84 180 top
C359  EV@22u/6.3V_6  [C0603]  108.01 120.38 180 bottom
C360  EV@4.7u/6.3V_4  [C0402_2]  120.58 116.7 0 bottom
C362  EV@1u/6.3V_4  [C0402]  109.03 109.08 90 top
C363  EV@10u/6.3V_4  [C0402]  118.93 121.53 0 bottom
C364  *EV@0.1u/16V_4  [C0402]  100.26 125.34 0 bottom
C365  EV@1u/6.3V_4  [C0402]  104.07 102.35 270 top
C366  EV@4.7u/6.3V_4  [C0402_2]  110.55 108.83 180 top
C367  EV@4.7u/6.3V_4  [C0402_2]  108.16 102.35 270 top
C368  EV@4.7u/6.3V_4  [C0402_2]  100.65 105.14 270 top
C369  EV@4.7u/6.3V_4  [C0402_2]  105.6 100.82 0 top
C370  EV@0.22u/10V_4  [C0402]  98.11 110.81 180 top
C371  EV@0.1u/16V_4  [C0402]  100.52 98.61 270 top
C372  EV@4.7u/6.3V_4  [C0402_2]  107.38 100.82 180 top
C373  EV@4.7u/6.3V_4  [C0402_2]  101.84 102.35 270 top
C374  EV@4.7u/6.3V_4  [C0402_2]  107 105.95 270 top
C375  EV@0.1u/16V_4  [C0402]  102.78 98.54 90 top
C376  EV@4.7u/6.3V_4  [C0402_2]  100.39 96.86 90 top
C377  EV@22U/6.3VS_4  [C0402]  118.3 118.22 90 bottom
C378  EV@1u/6.3V_4  [C0402]  101.48 98.61 270 top
C379  EV@4.7u/6.3V_4  [C0402_2]  120.58 115.43 0 bottom
C380  EV@4.7u/6.3V_4  [C0402_2]  105.57 98.31 0 top
C381  EV@10u/6.3V_4  [C0402]  120.33 118.22 90 bottom
C382  EV@0.22u/10V_4  [C0402]  102.04 119.24 90 top
C383  EV@10u/6.3V_4  [C0402]  119.31 118.22 90 bottom
C384  EV@0.22u/10V_4  [C0402]  101.03 119.24 90 top
C385  EV@220u/2V_7343H1.0  [CC7343]  110.25 123.56 180 top
C386  EV@22u/6.3V_6  [C0603]  103.97 98.82 90 top
C387  EV@47U/6.3V_6  [C0603]  103.72 119.09 180 bottom
C388  EV@10u/6.3V_4  [C0402]  109.49 117.74 180 bottom
C389  *EV@10u/6.3V_4  [C0402]  116.52 123.68 0 bottom
C391  *EV@10u/6.3V_4  [C0402]  116.52 124.7 0 bottom
C392  EV@4.7u/6.3V_4  [C0402_2]  89.09 103.49 180 top
C393  *EV@10u/6.3V_4  [C0402]  106.87 117.84 0 bottom
C394  EV@1u/6.3V_4  [C0402]  97.47 99.94 270 top
C395  EV@1u/6.3V_4  [C0402]  101.28 110.86 270 top
C396  EV@4.7u/6.3V_4  [C0402_2]  106.87 118.99 0 bottom
C397  EV@4.7u/6.3V_4  [C0402_2]  113.35 118.96 180 bottom
C398  EV@0.1u/16V_4  [C0402]  99.4 99.81 270 top
C399  EV@1u/6.3V_4  [C0402]  110.25 110.88 270 top
C400  EV@4.7u/6.3V_4  [C0402_2]  111.29 118.48 0 bottom
C401  EV@0.1u/16V_4  [C0402]  98.44 99.81 270 top
C402  EV@1u/6.3V_4  [C0402]  102.68 108.7 90 top
C403  EV@4.7u/6.3V_4  [C0402_2]  109.49 118.88 180 bottom
C406  EV@4.7u/6.3V_4  [C0402_2]  101.84 100.57 90 top
C407  EV@4.7u/6.3V_4  [C0402_2]  103.57 100.75 180 top
C408  EV@4.7u/6.3V_4  [C0402_2]  101.87 106.29 270 top
C409  EV@4.7u/6.3V_4  [C0402_2]  101.84 104.13 90 top
C410  EV@1u/6.3V_4  [C0402]  107.5 107.73 0 top
C411  EV@1u/6.3V_4  [C0402]  105.17 104.13 90 top
C412  EV@10u/6.3V_4  [C0402]  106.97 102.35 270 top
C413  EV@47U/6.3V_6  [C0603]  116.9 119.49 180 top
C414  *EV@47U/6.3V_6  [C0603]  106.74 120.48 180 top
C415  EV@10u/6.3V_4  [C0402]  100.77 107.43 270 top
C416  EV@47U/6.3V_6  [C0603]  110.3 119.06 180 top
C417  *EV@47U/6.3V_6  [C0603]  116.9 122.8 180 top
C418  EV@10u/6.3V_4  [C0402]  106.97 104.13 90 top
C419  EV@47U/6.3V_6  [C0603]  104.58 109.21 0 top
C420  *EV@47U/6.3V_6  [C0603]  89.98 115.94 180 bottom
C421  EV@10u/6.3V_4  [C0402]  105.17 102.35 270 top
C422  EV@47U/6.3V_6  [C0603]  97.98 105.27 90 top
C423  *EV@47U/6.3V_6  [C0603]  110.3 120.48 0 top
C424  EV@10u/6.3V_4  [C0402]  105.17 105.9 270 top
C425  EV@0.1u/16V_4  [C0402]  99.76 107.99 270 top
C426  EV@47U/6.3V_6  [C0603]  106.74 118.96 0 top
C427  *EV@47U/6.3V_6  [C0603]  116.9 121.14 0 top
C428  EV@10u/6.3V_4  [C0402]  105.6 107.94 0 top
C429  EV@4.7u/6.3V_4  [C0402_2]  99.81 109.76 90 top
C430  EV@10u/6.3V_4  [C0402]  104.07 104.13 90 top
C431  EV@4.7u/6.3V_4  [C0402_2]  98.59 107.68 270 top
C432  EV@10u/6.3V_4  [C0402]  99.38 105.9 90 top
C433  EV@0.1u/16V_4  [C0402]  98.21 121.45 180 bottom
C438  EV@1u/6.3V_4  [C0402]  121.83 93.59 90 top
C439  EV@1u/6.3V_4  [C0402]  110.3 104.79 180 top
C440  EV@1u/6.3V_4  [C0402]  123.12 93.59 90 top
C441  EV@1u/6.3V_4  [C0402]  139.38 105.02 90 top
C442  EV@1u/6.3V_4  [C0402]  136.21 105.02 90 top
C443  EV@10u/6.3V_4  [C0402]  109.41 100.44 180 top
C444  EV@10u/6.3V_4  [C0402]  110.31 103.81 180 top
C445  *EV@22U/6.3V_6  [C0603]  109.94 106.95 180 top
C446  *EV@22U/6.3V_6  [C0603]  121.09 102.73 90 bottom
C447  EV@1u/6.3V_4  [C0402]  109.41 99.43 180 top
C448  EV@10u/6.3V_4  [C0402]  110.3 105.75 180 top
C449  EV@1u/6.3V_4  [C0402]  108.42 98.41 180 top
C450  EV@1u/6.3V_4  [C0402]  107.06 99.17 90 top
C451  EV@22u/6.3V_6  [C0603]  119.44 102.73 90 bottom
C452  EV@0.1u/16V_4  [C0402]  101.79 123.81 90 bottom
C453  EV@22u/6.3V_4  [C0402_2]  110.17 98.28 180 top
C454  EV@0.1u/16V_4  [C0402]  111.06 102.48 0 top
C455  EV@0.1u/16V_4  [C0402]  106.36 97.22 180 top
C456  EV@0.1u/16V_4  [C0402]  89.85 99.94 0 top
C457  EV@0.1u/16V_4  [C0402]  89.85 106.03 0 top
C458  *EV@22u/6.3V_4  [C0402_2]  98.87 101.28 0 top
C459  EV@0.1u/16V_4  [C0402]  100.1 103.33 0 top
C460  EV@0.1u/16V_4  [C0402]  100.1 102.37 0 top
C461  *EV@10u/6.3V_4  [C0402]  89.85 107.56 180 top
C462  *EV@47U/6.3V_6  [C0603]  86.68 102.22 0 top
C463  EV@12p/50V_4  [C0402]  101.92 88.89 180 bottom
C464  EV@12p/50V_4  [C0402]  100.14 88.89 0 bottom
C471  EV@22u/6.3V_6  [C0603]  142.25 116.62 270 top
C472  EV@22u/6.3V_6  [C0603]  136.71 95.74 0 top
C473  EV@22u/6.3V_6  [C0603]  137.09 79.74 180 bottom
C474  EV@22u/6.3V_6  [C0603]  123 117.82 0 bottom
C475  EV@22u/6.3V_6  [C0603]  126.81 104.51 0 top
C476  EV@22u/6.3V_6  [C0603]  120.46 96 90 bottom
C477  EV@1u/6.3V_4  [C0402]  128.59 106.03 180 top
C478  EV@1u/6.3V_4  [C0402]  138.87 86.85 0 top
C479  EV@1u/6.3V_4  [C0402]  132.04 90.79 270 top
C480  EV@1u/6.3V_4  [C0402]  132.01 113.27 270 top
C481  EV@1u/6.3V_4  [C0402]  134.94 115.18 180 top
C482  EV@1u/6.3V_4  [C0402]  134.68 108.83 90 top
C483  EV@1u/6.3V_4  [C0402]  127.57 86.73 270 top
C484  EV@10u/6.3V_4  [C0402]  139.38 109.08 270 top
C485  *EV@22U/6.3V_6  [C0603]  140.83 116.62 270 top
C486  *EV@22U/6.3V_6  [C0603]  123 116.32 0 bottom
C487  EV@22u/6.3V_6  [C0603]  127.52 120.53 270 bottom
C488  EV@22u/6.3V_6  [C0603]  136.71 97.65 0 top
C489  EV@22u/6.3V_6  [C0603]  123 114.79 0 bottom
C490  EV@22u/6.3V_6  [C0603]  121.98 96 90 bottom
C491  EV@1u/6.3V_4  [C0402]  139.89 93.59 0 top
C492  EV@1u/6.3V_4  [C0402]  131.51 116.83 90 top
C493  EV@1u/6.3V_4  [C0402]  134.68 117.21 180 top
C494  EV@1u/6.3V_4  [C0402]  130.62 92.19 270 top
C495  EV@1u/6.3V_4  [C0402]  130.36 108.44 0 top
C496  EV@1u/6.3V_4  [C0402]  130.74 86.73 90 top
C497  EV@1u/6.3V_4  [C0402]  131.76 80 0 bottom
C498  EV@1u/6.3V_4  [C0402]  138.11 112.76 0 top
C499  EV@1u/6.3V_4  [C0402]  129.86 80 180 bottom
C500  EV@10u/6.3V_4  [C0402]  137.35 117.46 180 top
C501  EV@10u/6.3V_4  [C0402]  136.46 90.28 0 top
C502  EV@10u/6.3V_4  [C0402]  128.59 90.92 180 top
C503  *EV@22U/6.3V_6  [C0603]  123.51 96 90 bottom
C504  *EV@22U/6.3V_6  [C0603]  134.05 79.74 180 bottom
C505  EV@820p/50V_4  [C0402]  133.92 98.03 180 top
C506  EV@820p/50V_4  [C0402]  132.65 103.11 0 top
C508  TPC@1u/10V_4  [C0402]  17.08 45.71 0 top
C509  TPC@100u/6.3V_12  [C1206]  18.86 53.07 0 bottom
C510  TPC@470p/50V_4  [C0402]  17.05 50.46 180 top
C511  TPC@0.1u/16V_4  [C0402]  17.05 51.47 180 top
C512  1u/6.3V_4  [C0402]  22.59 42.12 90 bottom
C513  *1.6p/50V_4  [C0402]  24.37 53.07 270 top
C514  0.1u/16V_4  [C0402]  17.84 57.26 0 bottom
C515  470p/50V_4  [C0402]  15.17 43.8 180 bottom
C516  0.1u/16V_4  [C0402]  15.17 44.94 180 bottom
C517  100u/6.3V_12  [C1206]  18.98 41.39 0 bottom
C518  *1.6p/50V_4  [C0402]  24.37 54.85 90 top
C519  0.1u/16V_4  [C0402]  25.72 57.64 0 top
C520  0.1u/16V_4  [C0402]  25.72 58.66 0 top
C521  *1.6p/50V_4  [C0402]  22.16 57.26 90 top
C522  *1.6p/50V_4  [C0402]  22.16 59.04 270 top
C523  *1.6p/50V_4  [C0402]  23.56 31.74 270 top
C524  1u/6.3V_4  [C0402]  203.72 21.2 90 bottom
C525  0.1u/16V_4  [C0402]  15.17 42.66 180 bottom
C526  *1.6p/50V_4  [C0402]  23.56 33.51 90 top
C527  470p/50V_4  [C0402]  210.3 23.46 270 bottom
C528  0.1u/16V_4  [C0402]  211.26 23.35 270 bottom
C529  *100u/6.3V_12  [C1206]  206.08 24.27 180 bottom
C530  0.1u/16V_4  [C0402]  24.45 36.94 0 top
C531  0.1u/16V_4  [C0402]  24.45 37.96 0 top
C532  *1.6p/50V_4  [C0402]  21.27 36.56 90 top
C533  *1.6p/50V_4  [C0402]  21.27 38.34 270 top
C536  0.1u/25V_4  [C0402]  64.58 105.9 90 bottom
C537  0.01u/50V_4  [C0402]  65.97 106.54 270 bottom
C542  4.7u/25V_6  [C0603]  67.37 110.1 270 bottom
C543  *0.047u/25V_4  [C0402]  60.39 104.38 270 bottom
C544  *0.047u/25V_4  [C0402]  61.4 104.38 270 bottom
C545  *22U/6.3V_6  [C0603]  62.47 99.94 180 top
C546  0.1u/16V_4  [C0402]  57.54 103.24 180 bottom
C547  10P/50V_4  [C0402]  42.48 105.4 270 bottom
C548  10P/50V_4  [C0402]  41.34 105.4 270 bottom
C550  0.1u/16V_4  [C0402]  62.06 101.13 180 top
C552  0.1u/16V_4  [C0402]  55.21 104.38 90 bottom
C553  0.1u/16V_4  [C0402]  54.19 104.38 90 bottom
C554  0.1u/16V_4  [C0402]  53.22 104.38 90 bottom
C555  0.1u/16V_4  [C0402]  52.21 104.38 90 bottom
C556  0.1u/16V_4  [C0402]  62.7 109.33 180 top
C557  0.1u/16V_4  [C0402]  62.7 108.06 180 top
C558  33p/50V_4  [C0402]  56.22 107.3 270 top
C559  1u/6.3V_4  [C0402]  83.88 98.06 270 bottom
C560  0.01u/50V_4  [C0402]  77.4 95.87 90 bottom
C561  0.1u/16V_4  [C0402]  79.44 95.87 90 bottom
C562  10u/6.3V_4  [C0402]  78.42 95.87 90 bottom
C563  2.2u/6.3V_4  [C0402]  204.13 39.76 90 bottom
C564  10u/6.3V_4  [C0402_2]  202.07 38.37 270 bottom
C565  10u/6.3V_6  [C0603]  208.09 37.25 270 bottom
C566  1u/10V_6  [C0603]  207.99 39.97 180 bottom
C567  1u/10V_6  [C0603]  206.67 37.93 270 bottom
C568  0.1u/16V_4  [C0402]  200.98 37.71 270 bottom
C569  10u/6.3V_4  [C0402_2]  199.63 37.07 0 bottom
C572  10u/6.3V_4  [C0402_2]  209.51 36.18 90 bottom
C573  10u/6.3V_4  [C0402_2]  199.15 33.41 0 bottom
C574  10u/6.3V_4  [C0402_2]  210.88 31.48 180 bottom
C575  0.1u/16V_4  [C0402]  210.88 32.63 180 bottom
C576  10u/6.3V_4  [C0402_2]  210.65 29.3 180 bottom
C577  0.1u/16V_4  [C0402]  210.73 30.39 180 bottom
C578  10u/6.3V_4  [C0402_2]  203.52 27.37 90 bottom
C580  0.1u/16V_4  [C0402]  209.13 28.18 270 bottom
C581  10u/6.3V_4  [C0402_2]  211.42 26.66 180 bottom
C583  33p/50V_4  [C0402]  208.32 26.78 0 bottom
C584  0.1u/16V_4  [C0402]  202.42 27.32 90 bottom
C585  10u/6.3V_4  [C0402_2]  203.76 27.49 90 top
C586  *1000p/50V_4  [C0402]  210.63 39.86 180 top
C587  *22p/50V_4  [C0402]  204.61 27.32 270 bottom
C588  *0.1u/16V_4  [C0402]  197.52 31.36 0 bottom
C589  4.7u/6.3V_6  [C0603]  211.14 43.8 270 top
C590  100p/50V_4  [C0402]  215.78 42.1 270 top
C591  100p/50V_4  [C0402]  215.76 43.83 270 top
C592  100p/50V_4  [C0402]  215.38 46.19 0 top
C593  100p/50V_4  [C0402]  215.38 47.53 0 top
C594  4.7u/6.3V_6  [C0603]  209.64 43.78 270 top
C595  *1u/10V_4  [C0402]  210.73 30.39 180 top
C596  *0.1u/16V_4  [C0402]  206.54 30.24 180 top
C597  *10u/6.3V_6  [C0603]  204.35 30.03 180 top
C598  *10u/6.3V_6  [C0603]  199.32 30.85 180 top
C599  *0.1u/16V_4  [C0402]  200.24 32.04 0 top
C601  1000p/50V_4  [C0402]  119.06 21.45 270 top
C602  1000p/50V_4  [C0402]  118.04 21.45 270 top
C603  1000p/50V_4  [C0402]  116.9 21.45 270 top
C604  1000p/50V_4  [C0402]  115.76 21.47 270 top
C613  *10P/50V_4  [C0402]  22.67 62.6 90 top
C614  *10P/50V_4  [C0402]  22.67 64.38 270 top
C616  220p/50V_4  [C0402]  14.92 83.93 180 top
C618  HDMI_R@0.1u/16V_4  [C0402]  18.1 74.92 180 top
C619  HDMI_R@0.1u/16V_4  [C0402]  22.85 81.77 90 bottom
C628  HDMI_R@0.1u/16V_4  [C0402]  23.56 82.66 0 top
C631  0.1u/16V_4  [C0402]  40.12 106.56 270 top
C632  0.1u/16V_4  [C0402]  49.87 107.56 180 top
C633  0.1u/16V_4  [C0402]  49.59 106.54 180 top
C634  0.1u/16V_4  [C0402]  43.37 109.08 0 top
C635  1u/6.3V_4  [C0402]  40.45 102.81 270 top
C636  0.1u/16V_4  [C0402]  43.37 110.1 0 top
C637  0.1u/16V_4  [C0402]  48.58 102.86 180 top
C638  15p/50V_4  [C0402]  46.16 111.24 0 top
C639  15p/50V_4  [C0402]  44.38 111.24 0 top
C640  0.1u/16V_4  [C0402]  48.58 101.84 180 top
C641  0.1u/16V_4  [C0402]  41.29 109.46 0 top
C642  0.1u/16V_4  [C0402]  41.29 108.44 0 top
C643  *4.7u/6.3V_4  [C0402_2]  41.08 111.85 270 top
C644  *4.7u/6.3V_4  [C0402_2]  39.89 111.82 270 top
C645  0.01u/50V_4  [C0402]  29.53 102.35 180 top
C646  10p/3KV_1808  [CC1808]  21.4 112.51 234 bottom
C664  *0.1U/16V_4  [C0402]  212.23 23.33 270 bottom
C665  *22U/6.3V_6  [C0603]  209.1 24.98 270 bottom
C675  TPC@0.1u/25V_4  [C0402]  9.99 20.03 0 top
C676  TPC@0.1u/25V_4  [C0402]  10.22 13.45 270 top
C677  TPC@0.1u/16V_4  [C0402]  21.2 22.25 180 bottom
C680  TPC@0.1u/16V_4  [C0402]  17.59 25.26 90 bottom
C681  TPC@0.1u/16V_4  [C0402]  21.2 23.26 180 bottom
C682  TPC@0.1u/16V_4  [C0402]  21.55 21.2 180 bottom
C683  TPC@0.1u/16V_4  [C0402]  21.55 20.18 180 bottom
C684  TPC@0.1u/16V_4  [C0402]  18.6 25.26 90 bottom
C685  TPC@0.1u/16V_4  [C0402]  14.54 19.04 270 bottom
C686  TPC@0.1u/16V_4  [C0402]  15.56 19.04 270 bottom
C691  *TPC@390p/50V_4  [C0402]  11.36 18.4 0 top
C692  *TPC@390p/50V_4  [C0402]  10.22 13.45 270 bottom
C695  0.1u/16V_4  [C0402]  68.77 23.48 180 bottom
C696  10P/50V_4  [C0402]  67.96 23.1 90 top
C697  10P/50V_4  [C0402]  73.24 21.6 0 top
C698  *10P/50V_4  [C0402]  73.72 19.42 180 top
C699  *10P/50V_4  [C0402]  70.55 21.7 180 top
C706  220p/25V_2  [C0201]  156.75 20.15 90 top
C707  220p/25V_2  [C0201]  156.04 20.15 90 top
C708  220p/25V_2  [C0201]  153.1 20.53 90 top
C709  220p/25V_2  [C0201]  157.47 20.15 90 top
C711  220p/25V_2  [C0201]  158.18 20.15 90 top
C713  220p/25V_2  [C0201]  159.6 20.15 90 top
C714  220p/25V_2  [C0201]  158.89 20.15 90 top
C715  220p/25V_2  [C0201]  160.31 20.15 90 top
C716  220p/25V_2  [C0201]  151.57 20.53 90 top
C717  220p/25V_2  [C0201]  152.33 20.53 90 top
C718  220p/25V_2  [C0201]  153.86 20.53 90 top
C719  220p/25V_2  [C0201]  150.81 20.53 90 top
C720  220p/25V_2  [C0201]  170.29 20.89 270 top
C721  220p/25V_2  [C0201]  171.72 20.89 270 top
C722  220p/25V_2  [C0201]  169.58 20.86 270 top
C723  220p/25V_2  [C0201]  168.87 20.86 270 top
C724  220p/25V_2  [C0201]  172.43 20.89 270 top
C725  220p/25V_2  [C0201]  168.16 20.86 270 top
C726  220p/25V_2  [C0201]  171 20.89 270 top
C727  220p/25V_2  [C0201]  167.45 20.31 90 top
C728  220p/25V_2  [C0201]  161.02 20.15 90 top
C729  220p/25V_2  [C0201]  161.73 20.15 90 top
C730  220p/25V_2  [C0201]  162.44 20.15 90 top
C731  220p/25V_2  [C0201]  166.74 20.31 90 top
C732  220p/25V_2  [C0201]  149.9 20.94 0 top
C733  220p/25V_2  [C0201]  149.9 22.21 0 top
C734  *KBL@2.2u/6.3V_6  [C0603]  197.83 17.82 90 bottom
C735  *0.1U/16V_4  [C0402]  158.05 29.2 0 top
C736  KBL@4.7u/6.3V_6  [C0603]  197.29 11.42 270 bottom
C737  KBL@0.01u/50V_4  [C0402]  200.21 15.23 90 bottom
C740  TPM@10u/6.3V_6  [C0603]  130.44 22.47 270 top
C741  TPM@0.1u/10V_2  [C0201]  121.12 19.42 270 top
C742  TPM@0.1u/10V_2  [C0201]  131.51 22.34 90 top
C743  TPM@10u/6.3V_6  [C0603]  130.52 17.51 90 top
C744  TPM@0.1u/10V_2  [C0201]  121.83 19.42 270 top
C745  TPM@0.1u/10V_2  [C0201]  129.45 17.64 270 top
C749  *PBA@2.2u/16V_6  [C0603]  47.05 20.05 180 top
C750  *PBA@0.01u/50V_4  [C0402]  52.64 20.43 90 top
C752  PBA@4.7u/6.3V_4  [C0402_2]  50.02 16.5 270 top
C753  PBA@0.01u/50V_4  [C0402]  48.88 16.62 270 top
C770  *10u/6.3V_4  [C0402_2]  214.56 12.94 0 top
C771  10u/6.3V_4  [C0402_2]  214.56 14.21 0 top
C772  0.1u/16V_4  [C0402]  214.56 15.35 0 top
C773  ODD@0.01u/50V_4  [C0402]  132.65 21.58 90 bottom
C774  ODD@0.01u/50V_4  [C0402]  131.63 21.58 90 bottom
C775  *ODD@0.1u/16V_4  [C0402]  130.62 21.58 90 bottom
C776  *ODD@0.1u/16V_4  [C0402]  129.6 21.58 90 bottom
C777  ODD@10u/6.3V_6  [C0603]  128.33 21.58 270 bottom
C778  *ODD@100u/6.3V_12  [C1206]  126.43 22.34 270 bottom
C779  *ODD@15p/50V_4  [C0402]  138.49 20.69 270 bottom
C780  ODD@180p/50V_4  [C0402]  139.13 19.16 0 bottom
C781  ODD@0.01u/50V_4  [C0402]  133.64 21.2 270 bottom
C782  ODD@0.01u/50V_4  [C0402]  134.61 21.2 270 bottom
C783  ODD@0.01u/50V_4  [C0402]  136.13 21.32 270 bottom
C784  ODD@0.01u/50V_4  [C0402]  137.09 21.32 270 bottom
C785  *SSD@0.1u/16V_2  [C0201]  38.92 4.43 270 top
C786  SSD@0.1u/16V_2  [C0201]  36.26 4.43 270 top
C788  SSD@0.22u/10V_4  [C0402]  36 9.64 90 top
C789  SSD@0.22u/10V_4  [C0402]  34.99 9.64 90 top
C790  SSD@0.22u/10V_4  [C0402]  33.97 9.64 90 top
C791  SSD@0.22u/10V_4  [C0402]  32.95 9.64 90 top
C792  SSD@0.22u/10V_4  [C0402]  31.56 9.64 90 top
C793  SSD@0.22u/10V_4  [C0402]  30.54 9.64 90 top
C794  SSD@0.22u/10V_4  [C0402]  28.64 9.64 90 top
C795  SSD@0.22u/10V_4  [C0402]  27.62 9.64 90 top
C800  *0.1u/16V_2  [C0201]  192.52 30.49 90 bottom
C801  0.1u/16V_2  [C0201]  193.23 30.44 90 bottom
C802  10u/6.3V_4  [C0402_2]  194.45 30.47 180 bottom
C804  0.1u/16V_2  [C0201]  193.1 11.04 270 bottom
C805  10u/6.3V_4  [C0402_2]  195.64 11.04 270 bottom
C841  *0.1u/6.3V_2  [C0201]  39.76 123.02 90 bottom
C842  0.1u/16V_4  [C0402]  38.8 119.98 0 bottom
C843  256@0.1u/16V_4  [C0402]  197.55 32.32 0 bottom
C844  100p/50V_4  [C0402]  196.84 30.01 270 bottom
C845  10u/6.3V_4  [C0402_2]  210.02 38.44 270 bottom
C846  255@0.1u/16V_4  [C0402]  200.16 27.32 270 bottom
C847  HDMI_R@0.1u/10V_2  [C0201]  25.77 80.63 180 top
C848  HDMI_R@0.1u/10V_2  [C0201]  25.77 76.82 180 top
C849  HDMI_R@0.1u/10V_2  [C0201]  25.77 81.77 180 top
C850  HDMI_R@0.1u/10V_2  [C0201]  25.77 78.73 180 top
C851  HDMI_R@0.1u/10V_2  [C0201]  25.77 77.96 180 top
C852  HDMI_R@0.1u/10V_2  [C0201]  25.77 76.06 180 top
C853  HDMI_R@0.1u/10V_2  [C0201]  25.77 74.92 180 top
C854  HDMI_R@0.1u/10V_2  [C0201]  25.77 79.87 180 top
C1044  *0.1u/25V_6  [C0603]  21.65 40.63 90 top
C1189  0.1u/10V_2  [C0201]  179.64 25.23 270 top
C1190  0.1u/10V_2  [C0201]  179.67 24.22 90 top
C1208  180p/50V_4  [C0402]  201.86 23.94 0 top
C1210  180p/50V_4  [C0402]  201.81 22.97 180 top
C1211  1u/6.3V_2  [C0201]  50.28 26.4 270 top
C1214  1u/6.3V_2  [C0201]  46.04 27.29 180 top
C1217  1u/6.3V_2  [C0201]  50.35 25.01 90 top
C1675  0.1u/16V_4  [C0402]  50.23 104.38 90 bottom
C1676  0.1u/16V_4  [C0402]  51.24 104.38 90 bottom
C1677  0.1u/16V_4  [C0402]  49.21 105.14 90 bottom
C1678  0.1u/16V_4  [C0402]  48.19 105.14 90 bottom
C1679  HDMI_N@0.1u/10V_2  [C0201]  15.56 79.97 180 bottom
C1680  HDMI_N@0.1u/10V_2  [C0201]  15.56 76.16 180 bottom
C1681  HDMI_N@0.1u/10V_2  [C0201]  15.56 81.16 180 bottom
C1682  HDMI_N@0.1u/10V_2  [C0201]  15.56 78.07 180 bottom
C1683  HDMI_N@0.1u/10V_2  [C0201]  15.56 77.35 180 bottom
C1684  HDMI_N@0.1u/10V_2  [C0201]  15.56 75.45 180 bottom
C1685  HDMI_N@0.1u/10V_2  [C0201]  15.56 74.26 180 bottom
C1686  HDMI_N@0.1u/10V_2  [C0201]  15.56 79.26 180 bottom
C1687  *HDMI_R@0.1u/16V_4  [C0402]  25.08 84.31 270 top
C1688  HDMI_R@0.1u/16V_4  [C0402]  26.22 73.11 180 top
C1689  HDMI_R@0.1u/16V_4  [C0402]  26.22 74.08 180 top
C1690  *HDMI_R@0.1u/16V_4  [C0402]  24.06 84.31 270 top
C1691  HDMI_R@0.1u/16V_4  [C0402]  22.46 83.17 0 bottom
C1692  *HDMI_R@0.1u/16V_4  [C0402]  25.33 68.57 180 top
C1693  HDMI_R@0.1u/16V_4  [C0402]  26.1 84.31 270 top
C2374  180p/50V_4  [C0402]  181.27 19.8 0 top
C2607  180p/50V_4  [C0402]  200.98 27.98 180 top
C2609  0.1u/16V_2  [C0201]  192.21 11.04 270 bottom
C2610  0.1u/16V_2  [C0201]  181.27 14.26 0 bottom
C2611  *0.1u/16V_2  [C0201]  193.86 11.04 270 bottom
C2612  *0.1u/16V_2  [C0201]  194.63 11.04 270 bottom
C2616  *SSD@0.1u/16V_2  [C0201]  23.18 4.43 180 top
C6502  TPC@47u/6.3V_8  [C0805]  29.25 19.04 270 bottom
C6503  *TPC@47u/6.3V_8  [C0805]  29.65 14.08 90 bottom
C6504  TPC@22u/6.3V_6  [C0603]  27.95 14.34 90 top
C6505  TPC@10u/25V_8  [C0805]  21.37 14.59 270 bottom
C6544  TPC@0.1u/16V_4  [C0402]  12.51 21.42 270 bottom
C6545  TPC@0.1u/16V_4  [C0402]  13.47 21.42 270 bottom
C6546  *TPC@0.1u/16V_4  [C0402]  14.44 21.42 270 bottom
C6547  TPC@0.1u/16V_4  [C0402]  27.75 18.02 270 top
C6548  TPC@22u/6.3V_6  [C0603]  27.87 14.34 90 bottom
C6549  TPC@22u/6.3V_6  [C0603]  29.4 14.34 90 top
C6550  0.22u/10V_2  [C0201]  104.33 45.22 0 bottom
C6551  0.22u/10V_2  [C0201]  101.28 44.54 0 bottom
C6552  0.22u/10V_2  [C0201]  104.33 45.96 0 bottom
C6553  0.22u/10V_2  [C0201]  101.28 43.8 0 bottom
C6554  EV@0.22u/10V_4  [C0402]  103.19 121.14 90 top
C6555  EV@0.22u/10V_4  [C0402]  103.31 119.24 90 top
C6556  EV@0.22u/10V_4  [C0402]  102.17 121.14 90 top
C6557  EV@0.22u/10V_4  [C0402]  104.33 119.24 90 top
C6559  0.01u/50V_4  [C0402]  28.89 89.78 90 top
C6560  *220p/50V_4  [C0402]  14.57 82.79 90 bottom
C6562  *10p/50V_4  [C0402]  178.07 23.58 180 top
C6563  180p/50V_4  [C0402]  183.3 31.43 180 top
C6564  10u/6.3V_6  [C0603]  201.79 14.46 0 top
C6565  0.1u/10V_2  [C0201]  200.37 26.86 270 top
C6566  0.1u/16V_4  [C0402]  200.65 19.54 270 top
C6568  180p/50V_4  [C0402]  198.94 10.81 0 top
C6569  0.1u/10V_2  [C0201]  192.11 11.67 270 top
C6570  0.1u/10V_2  [C0201]  191.4 11.67 270 top
C6571  1u/6.3V_4  [C0402]  178.5 22.21 270 top
C6572  180p/50V_4  [C0402]  182.97 29.12 0 top
C6573  0.1u/10V_2  [C0201]  185.1 31.36 180 top
C6574  0.1u/10V_2  [C0201]  187.03 32.29 90 top
C6575  0.1u/10V_2  [C0201]  191.4 32.24 90 top
C6577  0.1u/10V_2  [C0201]  180.88 17.99 270 top
C6578  0.1u/10V_2  [C0201]  181.62 17.99 270 top
C6580  180p/50V_4  [C0402]  197.12 31.86 90 top
C6581  TPC@150u/6.3V_3528H1.4  [C3528]  18.35 13.45 90 bottom
C6582  TPC@0.1u/25V_4  [C0402]  15.4 15.61 90 top
C6583  *TPC@0.1u/25V_4  [C0402]  11.62 3.92 270 top
C6584  TPC@0.1u/25V_4  [C0402]  20.36 17.69 90 top
C6586  HDD_R@0.01u/10V_2  [C0201]  212.51 19.93 90 top
C6587  HDD_R@0.01u/10V_2  [C0201]  211.14 19.93 90 top
C6588  HDD_R@0.01u/10V_2  [C0201]  210.37 19.93 90 top
C6589  HDD_R@0.01u/10V_2  [C0201]  209.1 19.93 90 top
C6590  HDD_N@0.01u/10V_2  [C0201]  213.04 12.11 270 top
C6591  HDD_N@0.01u/10V_2  [C0201]  211.77 12.11 270 top
C6592  HDD_N@0.01u/10V_2  [C0201]  210.88 12.11 270 top
C6593  HDD_N@0.01u/10V_2  [C0201]  209.61 12.11 270 top
C6594  HDD_R@0.01u/10V_2  [C0201]  213.04 12.56 90 top
C6595  HDD_R@0.01u/10V_2  [C0201]  211.77 12.56 90 top
C6596  HDD_R@0.01u/10V_2  [C0201]  210.88 12.56 90 top
C6597  HDD_R@0.01u/10V_2  [C0201]  209.61 12.56 90 top
C6598  HDD_R@0.1u/10V_2  [C0201]  215.07 16.37 270 top
C6599  HDD_R@0.1u/10V_2  [C0201]  214.31 16.37 270 top
C6600  HDD_R@0.1u/10V_2  [C0201]  208.47 12.1 0 top
C6601  HDD_R@0.1u/10V_2  [C0201]  215.83 16.37 270 top
C6602  HDD_R@0.1u/10V_2  [C0201]  208.5 12.81 0 top
C6603  GS@0.1u/10V_2  [C0201]  54.16 20.43 180 top
C6604  GS@33p/50V_4  [C0402]  62.29 19.34 90 top
C6605  GS@33p/50V_4  [C0402]  59.45 16.8 90 top
C6606  GS@0.1u/10V_2  [C0201]  55.76 27.7 90 top
C6607  HDD_R@10u/6.3V_4  [C0402_2]  208.06 11.14 180 top
C6608  GS@10u/6.3V_4  [C0402_2]  54.04 22.72 90 top
C6609  *0.1U/16V_2  [C0201]  92.26 22.08 0 bottom
C6610  0.1u/16V_4  [C0402]  180.48 20.99 0 top
C6612  0.1u/16V_2  [C0201]  94.42 37.88 270 top
C6613  0.1u/16V_2  [C0201]  99.12 31.23 90 top
C6614  0.1u/16V_2  [C0201]  97.8 25.77 180 bottom
C6615  0.1u/10V_2  [C0201]  171.77 23 90 bottom
